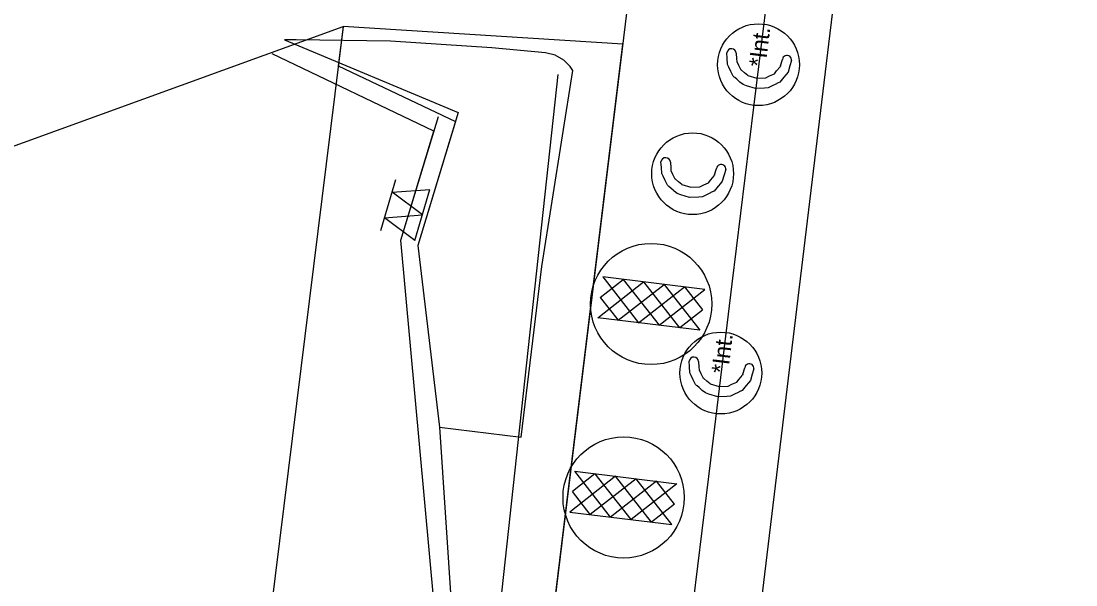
# Model space of a CAD drawing. Extents: x 400935 to 481562, y 415700 to 505362.
# Drawn here: x 481061.3 to 481357.9, y 490104.8 to 490263.4 of the extents above; entities that cross this region are included whole.
import ezdxf

# ---------------------------------------------------------------- set-up
doc = ezdxf.new("R2010")
doc.units = 0
for name, color, linetype in [('Coir Fiber Wattle with PAM Final CELL', 7, 'Continuous'), ('Earth Berm Final', 7, 'Continuous'), ('Label B CG CELL', 7, 'Continuous'), ('Matting on Slope Note Final CELL', 7, 'Continuous'), ('Old_Level_2', 7, 'Continuous'), ('Rock Silt Check Type A with Matting and PAM Final CELL', 7, 'Continuous'), ('Scratch_Level_3', 7, 'Continuous'), ('Scratch_Level_4', 7, 'Continuous'), ('Special Sediment Control Fence Section Both CELL', 7, 'Continuous'), ('Temporary Silt Fence Both', 7, 'Continuous'), ('Total Drainage Area Border Both Drainage', 7, 'Continuous')]:
    doc.layers.add(name, color=color, linetype=linetype)

msp = doc.modelspace()

# ---------------------------------------------------------------- linework, layer by layer
at = {"layer": 'Coir Fiber Wattle with PAM Final CELL'}
for p, q in [((481243.85, 490223.66), (481243.93, 490222.11)), ((481243.93, 490222.11), (481243.98, 490221.32)), ((481256.27, 490220.15), (481256.84, 490221.92)), ((481243.98, 490221.32), (481244.47, 490220.33)), ((481244.47, 490220.33), (481245.12, 490219.03)), ((481245.3, 490218.88), (481245.12, 490219.03)), ((481245.3, 490218.88), (481246.17, 490218.19)), ((481255.22, 490218.69), (481256.17, 490219.83)), ((481256.27, 490220.15), (481256.17, 490219.83)), ((481247.1, 490217.44), (481246.17, 490218.19)), ((481247.1, 490217.44), (481249.61, 490216.67)), ((481249.62, 490216.67), (481249.61, 490216.67)), ((481249.62, 490216.67), (481252.16, 490216.79)), ((481252.16, 490216.79), (481253.25, 490217.29)), ((481253.25, 490217.29), (481254.57, 490217.9)), ((481254.57, 490217.9), (481255.22, 490218.69))]:
    msp.add_line(p, q, dxfattribs=at)
msp.add_lwpolyline([(481259.41, 490221.6), (481258.96, 490220.11), (481258.44, 490218.37), (481257.9, 490217.73), (481257.26, 490216.95), (481256.12, 490215.57), (481256.08, 490215.55), (481255.69, 490215.35), (481255.62, 490215.32), (481254.76, 490214.9), (481254.16, 490214.6), (481252.85, 490213.96), (481251.81, 490213.89), (481249.26, 490213.72), (481249.25, 490213.72), (481246.74, 490214.52), (481245.76, 490214.84), (481244.9, 490215.57), (481244.72, 490215.73), (481243.99, 490216.35), (481243.43, 490216.83), (481243.3, 490216.94), (481243.02, 490217.18), (481243.02, 490217.18), (481242.36, 490218.54), (481241.77, 490219.75), (481241.42, 490220.48), (481241.3, 490222.23), (481241.19, 490223.78)], dxfattribs=at)
msp.add_circle((481250.1, 490220.44), 11.5, dxfattribs=at)
for centre, radius, start in [((481242.52, 490223.62), 1.33, 1.9239), ((481258.13, 490221.76), 1.3, 353.0365)]:
    msp.add_arc(centre, radius, start, 173.0365, dxfattribs=at)
at = {"layer": 'Earth Berm Final'}
msp.add_lwpolyline([(481212.19, 490248.38), (481198.72, 490124.18), (481186.82, 490014.53), (481173.7, 489911.46), (481166.37, 489853.86), (481164.05, 489799.4), (481163.89, 489759.7), (481165.78, 489717.82), (481170.64, 489667.3), (481174.33, 489615.2), (481173.71, 489567.81), (481171.39, 489523.3), (481166.26, 489479.02), (481158.82, 489435.07), (481154.27, 489408.23), (481147.12, 489381.96), (481137.73, 489356.4)], dxfattribs=at)
at = {"layer": 'Label B CG CELL'}
msp.add_line((481168.03, 490201.74), (481178.61, 490236.57), dxfattribs=at)
at = {"layer": 'Matting on Slope Note Final CELL'}
for p, q in [((481172.81, 490200.29), (481172.81, 490200.29)), ((481172.81, 490200.29), (481172.81, 490200.29)), ((481172.81, 490200.29), (481172.81, 490200.29)), ((481172.81, 490200.29), (481172.81, 490200.29)), ((481172.81, 490200.29), (481172.81, 490200.29)), ((481172.81, 490200.29), (481178.88, 490149.18)), ((481178.88, 490149.18), (481178.88, 490149.18)), ((481178.88, 490149.18), (481178.88, 490149.18)), ((481178.88, 490149.18), (481201.84, 490146.37))]:
    msp.add_line(p, q, dxfattribs=at)
msp.add_lwpolyline([(481201.84, 490146.37), (481207.7, 490194.38), (481216.44, 490249.47), (481215.7, 490250.59), (481213.86, 490252.42), (481211.42, 490253.81), (481208.71, 490254.44), (481193.62, 490255.85), (481165.16, 490257.73), (481138.63, 490258.13), (481135.32, 490258.12), (481135.32, 490258.12), (481135.32, 490258.12), (481135.32, 490258.12), (481135.32, 490258.12), (481135.32, 490258.12), (481135.32, 490258.12), (481135.32, 490258.12), (481184.15, 490237.62), (481172.81, 490200.29)], dxfattribs=at)
at = {"layer": 'Old_Level_2'}
for p, q in [((481262.36, 490254.31), (481262.44, 490252.76)), ((481262.44, 490252.76), (481262.49, 490251.97)), ((481262.49, 490251.97), (481262.98, 490250.99)), ((481274.78, 490250.8), (481275.35, 490252.57)), ((481262.98, 490250.99), (481263.63, 490249.69)), ((481263.81, 490249.54), (481263.63, 490249.69)), ((481263.81, 490249.54), (481264.68, 490248.84)), ((481265.61, 490248.1), (481264.68, 490248.84)), ((481271.76, 490247.95), (481273.08, 490248.56)), ((481273.08, 490248.56), (481273.73, 490249.35)), ((481273.73, 490249.35), (481274.68, 490250.49)), ((481274.78, 490250.8), (481274.68, 490250.49)), ((481265.61, 490248.1), (481268.12, 490247.33)), ((481268.13, 490247.32), (481268.12, 490247.33)), ((481268.13, 490247.32), (481270.67, 490247.44)), ((481270.67, 490247.44), (481271.76, 490247.95)), ((481251.77, 490167.61), (481251.85, 490166.06)), ((481251.85, 490166.06), (481251.9, 490165.27)), ((481264.19, 490164.1), (481264.76, 490165.87)), ((481251.9, 490165.27), (481252.39, 490164.29)), ((481252.39, 490164.29), (481253.04, 490162.99)), ((481253.22, 490162.84), (481253.04, 490162.99)), ((481253.22, 490162.84), (481254.09, 490162.14)), ((481262.49, 490161.86), (481263.14, 490162.65)), ((481263.14, 490162.65), (481264.09, 490163.78)), ((481264.19, 490164.1), (481264.09, 490163.78)), ((481255.02, 490161.39), (481254.09, 490162.14)), ((481255.02, 490161.39), (481257.53, 490160.62)), ((481257.54, 490160.62), (481257.53, 490160.62)), ((481257.54, 490160.62), (481260.08, 490160.74)), ((481260.08, 490160.74), (481261.17, 490161.25)), ((481261.17, 490161.25), (481262.49, 490161.86))]:
    msp.add_line(p, q, dxfattribs=at)
for points in [[(481277.92, 490252.26), (481277.47, 490250.77), (481276.95, 490249.03), (481276.41, 490248.38), (481275.77, 490247.61), (481274.63, 490246.22), (481274.59, 490246.2), (481274.19, 490246.01), (481274.13, 490245.97), (481273.27, 490245.55), (481272.67, 490245.26), (481271.36, 490244.61), (481270.32, 490244.54), (481267.77, 490244.37), (481267.76, 490244.38), (481265.25, 490245.18), (481264.27, 490245.5), (481263.41, 490246.23), (481263.23, 490246.38), (481262.5, 490247.01), (481261.94, 490247.48), (481261.81, 490247.6), (481261.53, 490247.83), (481261.53, 490247.84), (481260.87, 490249.2), (481260.28, 490250.41), (481259.93, 490251.14), (481259.81, 490252.89), (481259.7, 490254.43)], [(481267.33, 490165.56), (481266.88, 490164.07), (481266.36, 490162.33), (481265.82, 490161.68), (481265.18, 490160.9), (481264.04, 490159.52), (481264, 490159.5), (481263.61, 490159.31), (481263.54, 490159.27), (481262.68, 490158.85), (481262.08, 490158.56), (481260.77, 490157.91), (481259.73, 490157.84), (481257.18, 490157.67), (481257.17, 490157.67), (481254.66, 490158.48), (481253.68, 490158.79), (481252.82, 490159.53), (481252.64, 490159.68), (481251.91, 490160.31), (481251.35, 490160.78), (481251.22, 490160.89), (481250.94, 490161.13), (481250.94, 490161.14), (481250.28, 490162.5), (481249.7, 490163.7), (481249.34, 490164.43), (481249.22, 490166.19), (481249.11, 490167.73)]]:
    msp.add_lwpolyline(points, dxfattribs=at)
for centre in [(481268.61, 490251.1), (481258.02, 490164.39)]:
    msp.add_circle(centre, 11.5, dxfattribs=at)
for centre, radius, start in [((481261.03, 490254.27), 1.33, 1.9239), ((481276.64, 490252.42), 1.3, 353.0365), ((481250.44, 490167.57), 1.33, 1.9239), ((481266.05, 490165.72), 1.3, 353.0365)]:
    msp.add_arc(centre, radius, start, 173.0365, dxfattribs=at)
at = {"layer": 'Rock Silt Check Type A with Matting and PAM Final CELL'}
for p, q in [((481223.44, 490179.95), (481236.31, 490190.01)), ((481224.13, 490185.66), (481230.6, 490190.71)), ((481224.84, 490191.41), (481234.91, 490178.55)), ((481253.53, 490187.91), (481224.84, 490191.41)), ((481229.2, 490179.23), (481242.06, 490189.31)), ((481230.6, 490190.71), (481240.66, 490177.84)), ((481236.31, 490190.01), (481246.42, 490177.14)), ((481242.06, 490189.31), (481252.13, 490176.44)), ((481234.91, 490178.55), (481247.82, 490188.6)), ((481240.66, 490177.84), (481253.53, 490187.91)), ((481247.82, 490188.6), (481252.84, 490182.15)), ((481224.13, 490185.66), (481229.2, 490179.23)), ((481246.48, 490177.18), (481252.84, 490182.15)), ((481252.13, 490176.44), (481223.44, 490179.95)), ((481222.64, 490136.02), (481216.28, 490131.06)), ((481216.99, 490136.76), (481245.67, 490133.26)), ((481227.05, 490123.9), (481216.99, 490136.76)), ((481232.81, 490123.2), (481222.7, 490136.07)), ((481228.45, 490135.36), (481215.59, 490125.3)), ((481234.21, 490134.66), (481221.3, 490124.6)), ((481239.92, 490133.98), (481227.05, 490123.9)), ((481238.52, 490122.5), (481228.45, 490135.36)), ((481245.67, 490133.26), (481232.81, 490123.2)), ((481244.28, 490121.8), (481234.21, 490134.66)), ((481244.99, 490127.55), (481239.92, 490133.98)), ((481221.3, 490124.6), (481216.28, 490131.06)), ((481244.99, 490127.55), (481238.52, 490122.5)), ((481215.59, 490125.3), (481244.28, 490121.8))]:
    msp.add_line(p, q, dxfattribs=at)
for centre in [(481238.43, 490183.81), (481230.69, 490129.4)]:
    msp.add_circle(centre, 17.04, dxfattribs=at)
at = {"layer": 'Scratch_Level_3'}
msp.add_lwpolyline([(481230.94, 489941.33), (481237, 489990.96), (481243.06, 490040.59), (481249.13, 490090.22), (481255.19, 490139.86), (481261.25, 490189.49), (481267.31, 490239.12), (481273.37, 490288.75)], dxfattribs=at)
at = {"layer": 'Scratch_Level_4'}
msp.add_lwpolyline([(481192.51, 489946.27), (481250.03, 489939.44), (481357.88, 490832.14), (481301.55, 490839.02)], close=True, dxfattribs=at)
for points in [[(480877.24, 490463.31), (480982.54, 490200.49), (481151.83, 490261.85), (481107.68, 489905.23), (481078.42, 489657), (481066.69, 489412.89), (481003.5, 489522.94), (480707.43, 489791.02), (480585.75, 489869.24), (480505.56, 489977.09), (480447.46, 490122.86), (480351.3, 490280.03)], [(481167.24, 489780.17), (481170.35, 489851.13), (481181.18, 489944.23), (481192.1, 489942.89), (481230.44, 490256.86), (481151.83, 490261.85), (481150.47, 490250.81), (481183.39, 490235.11), (481172.81, 490200.29), (481178.88, 490149.18), (481182.3, 490098.39), (481173.21, 490049.12), (481168.48, 489999.33), (481146.66, 489951.62), (481133.08, 489902.91), (481123.89, 489853.66), (481122.2, 489803.5), (481124.96, 489752.79)]]:
    msp.add_lwpolyline(points, dxfattribs=at)
at = {"layer": 'Special Sediment Control Fence Section Both CELL'}
for p, q in [((481162.42, 490204.44), (481166.62, 490218.84)), ((481172.02, 490201.64), (481176.22, 490216.04))]:
    msp.add_line(p, q, dxfattribs=at)
for points in [[(481174.12, 490208.84), (481165.57, 490215.24), (481176.22, 490216.04)], [(481172.02, 490201.64), (481163.47, 490208.04), (481174.12, 490208.84)]]:
    msp.add_lwpolyline(points, dxfattribs=at)
at = {"layer": 'Temporary Silt Fence Both'}
for p, q in [((481177.36, 490232.45), (481131.82, 490254.17)), ((481168.03, 490201.74), (481177.36, 490232.45)), ((481177.39, 490099.29), (481168.03, 490201.74))]:
    msp.add_line(p, q, dxfattribs=at)
at = {"layer": 'Total Drainage Area Border Both Drainage'}
msp.add_lwpolyline([(481069.47, 489470.84), (481123.91, 489406.63), (481168.23, 489410.36), (481181.2, 489477.11), (481197.26, 489598.97), (481199.62, 489617.63), (481194.22, 489688.17), (481172.36, 489685.75), (481168.48, 489732.89), (481167.24, 489780.17), (481170.35, 489851.13), (481175.52, 489897.91), (481181.18, 489944.23), (481192.1, 489942.89), (481230.44, 490256.86), (481151.83, 490261.85), (481107.68, 489905.23), (481078.42, 489657)], close=True, dxfattribs=at)

# ---------------------------------------------------------------- texts
at = {"layer": 'Old_Level_2'}
for p in [(481270.58, 490250.26), (481260.06, 490164.05)]:
    msp.add_text('*Int.', height=4.746, rotation=83.0423, dxfattribs=at).set_placement(p)

doc.saveas('drawing.dxf')
